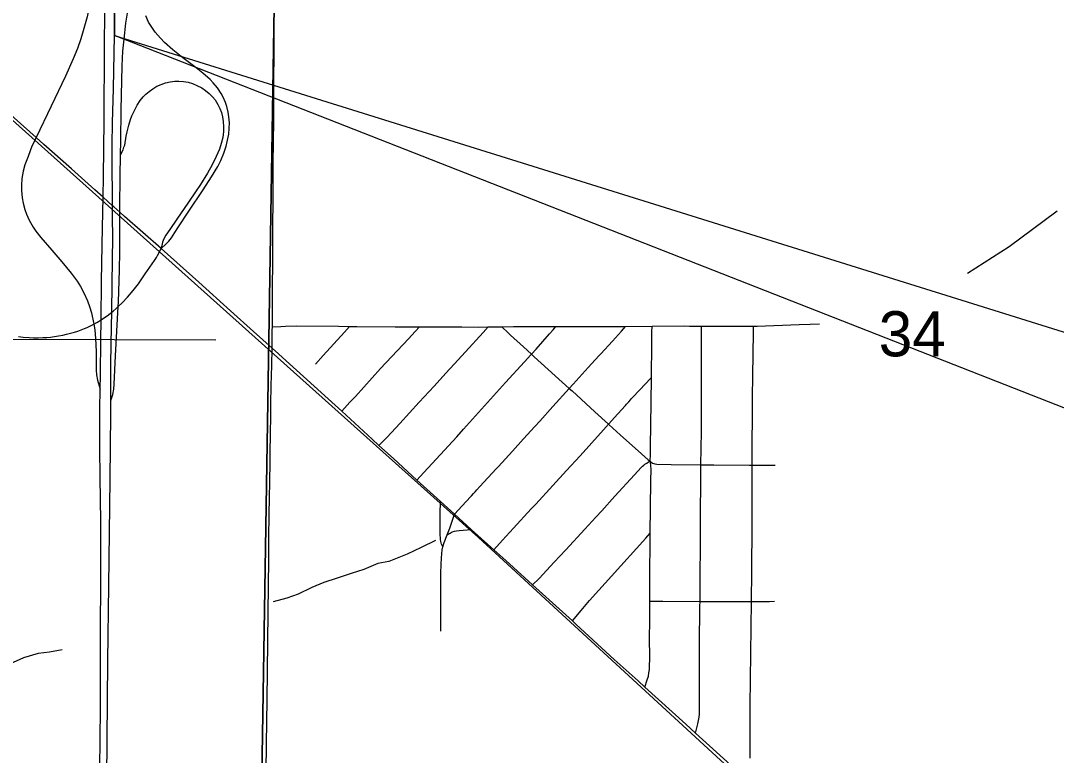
# Model space of a CAD drawing. Extents: x 0 to 40.2, y 0 to 22.
# Drawn here: x 5.526 to 6.486, y 16.354 to 17.035 of the extents above; entities that cross this region are included whole.
import ezdxf

# ---------------------------------------------------------------- set-up
doc = ezdxf.new("R2010")
doc.units = 0
for name, color, linetype in [('GM_X_Adjacent_County_Text', 7, 'Continuous'), ('GM_X_City_Street', 7, 'Continuous'), ('GM_X_Corporation', 7, 'Continuous'), ('GM_X_Major_Lake', 7, 'Continuous'), ('GM_X_Major_River', 7, 'Continuous'), ('GM_X_Major_River_Text', 7, 'Continuous'), ('GM_X_Minor_Lake', 7, 'Continuous'), ('GM_X_Rail_Line', 7, 'Continuous'), ('GM_X_Section', 7, 'Continuous'), ('GM_X_Unincorporated', 7, 'Continuous'), ('GM_X_Unincorporated_Location', 7, 'Continuous')]:
    doc.layers.add(name, color=color, linetype=linetype)

msp = doc.modelspace()

# ---------------------------------------------------------------- linework, layer by layer
at = {"layer": 'GM_X_Adjacent_County_Text'}
msp.add_lwpolyline([(5.61966, 17.93133), (5.62028, 17.89), (5.61863, 17.84377), (5.6183, 17.73735), (5.61781, 17.66349), (5.6165, 17.55078), (5.61518, 17.46691), (5.61644, 17.41988), (5.61626, 17.34851), (5.61494, 17.26994), (5.6143, 17.22476), (5.61361, 17.15512), (5.61332, 17.10722), (5.61328, 17.06369), (5.61294, 17.02079)], dxfattribs=at)
at = {"layer": 'GM_X_Corporation'}
for points in [[(4.77298, 17.26753), (5.76443, 17.25959), (5.74842, 16.25686), (4.77053, 16.2552)], [(5.76443, 17.25959), (6.76502, 17.25647), (6.76113, 16.25286), (5.74842, 16.25686)]]:
    msp.add_lwpolyline(points, close=True, dxfattribs=at)
at = {"layer": 'GM_X_Major_Lake'}
msp.add_line((5.65614, 16.82334), (5.62241, 16.85317), dxfattribs=at)
for points in [[(5.62241, 16.85317), (5.61791, 16.85715), (5.61248, 16.86195), (5.61128, 16.86303), (5.60244, 16.87093), (5.59485, 16.87772), (5.57314, 16.89725), (5.54749, 16.91986), (5.54029, 16.92629), (5.5053, 16.9575), (5.48725, 16.97355), (5.48411, 16.97635)], [(5.76512, 16.72562), (5.75908, 16.73104), (5.74185, 16.7465), (5.72053, 16.76558), (5.69106, 16.79227), (5.65614, 16.82334)], [(6.19712, 16.33296), (6.15175, 16.37401), (6.14259, 16.38229), (6.10475, 16.41674), (6.09846, 16.42246), (6.07632, 16.4425), (6.04104, 16.47484), (6.03748, 16.47807), (6.00059, 16.51153), (5.97564, 16.53414), (5.96454, 16.54407), (5.95293, 16.55446), (5.9438, 16.56279), (5.92823, 16.57701), (5.91528, 16.58882), (5.90883, 16.5947), (5.8934, 16.60874), (5.87159, 16.62859), (5.85809, 16.64083), (5.85177, 16.64657), (5.82371, 16.67254), (5.81755, 16.67823), (5.7689, 16.72223), (5.76512, 16.72562)]]:
    msp.add_lwpolyline(points, dxfattribs=at)
at = {"layer": 'GM_X_Major_River'}
msp.add_lwpolyline([(4.97994, 17.42091), (5.30245, 17.13578), (5.95038, 16.5554), (6.62714, 15.93274), (7.15702, 15.44764), (7.76806, 14.87866), (8.24495, 14.44186), (8.61841, 14.1)], dxfattribs=at)
at = {"layer": 'GM_X_Major_River_Text'}
for points in [[(5.59425, 17.08686), (5.59359, 17.07831), (5.59277, 17.06876), (5.58989, 17.04899), (5.58755, 17.03803), (5.58473, 17.02719), (5.58181, 17.01766), (5.57867, 17.00886), (5.5747, 16.99906), (5.56755, 16.98321), (5.55432, 16.95516), (5.54029, 16.92629)], [(5.60955, 16.68258), (5.61139, 16.68816), (5.6124, 16.69303), (5.61281, 16.69758), (5.61404, 16.72374), (5.61644, 16.76951), (5.61668, 16.774), (5.61772, 16.80318), (5.61801, 16.82058), (5.61791, 16.85715), (5.6179, 16.8622), (5.61829, 16.89016), (5.61868, 16.91027), (5.61892, 16.92308), (5.61924, 16.95167), (5.62023, 16.99266), (5.62086, 17.00632), (5.62186, 17.01745), (5.62364, 17.03226), (5.6256, 17.04516)], [(5.65614, 16.82334), (5.66067, 16.82747), (5.66327, 16.83008), (5.6658, 16.83318), (5.66885, 16.83824), (5.67177, 16.84265), (5.68208, 16.85804), (5.69536, 16.87759), (5.70306, 16.88966), (5.70867, 16.89937), (5.71148, 16.90491), (5.71444, 16.91176), (5.71657, 16.91827), (5.71793, 16.9237), (5.71888, 16.9292), (5.71943, 16.9348), (5.71951, 16.93977), (5.71915, 16.94536), (5.7185, 16.94966), (5.7172, 16.9551), (5.716, 16.95863), (5.7138, 16.96377), (5.71201, 16.96702), (5.70862, 16.97225), (5.70462, 16.97696), (5.70161, 16.98014), (5.69505, 16.98588), (5.68868, 16.99084), (5.67624, 17.00023), (5.66699, 17.00762), (5.65953, 17.01423), (5.65559, 17.0182), (5.65072, 17.02383), (5.64687, 17.02951), (5.64468, 17.03325), (5.64201, 17.03888)], [(5.61868, 16.91027), (5.62097, 16.91478), (5.62179, 16.91726), (5.62249, 16.91925), (5.62397, 16.92734), (5.62486, 16.93159), (5.62629, 16.93757), (5.62789, 16.94286), (5.6292, 16.94634), (5.6315, 16.95142), (5.63419, 16.95633), (5.63693, 16.96047), (5.63965, 16.96386), (5.64222, 16.96655), (5.64502, 16.969), (5.64857, 16.97151), (5.65233, 16.97369), (5.65628, 16.9755), (5.66039, 16.97692), (5.66462, 16.97791), (5.66893, 16.97845), (5.67265, 16.97855), (5.67698, 16.97824), (5.68126, 16.97745), (5.68542, 16.9762), (5.68945, 16.97456), (5.69384, 16.97223), (5.69746, 16.96982), (5.70084, 16.96708), (5.70391, 16.964), (5.70627, 16.96112), (5.70895, 16.95694), (5.7108, 16.95302), (5.71208, 16.94952), (5.71315, 16.9453), (5.71389, 16.94102), (5.71422, 16.93607), (5.71412, 16.93172), (5.71337, 16.92619), (5.71199, 16.92078), (5.71023, 16.91549), (5.7074, 16.90859), (5.70361, 16.90076), (5.69936, 16.89317), (5.69263, 16.88274), (5.68814, 16.87603), (5.68148, 16.86621)], [(5.54029, 16.92629), (5.53624, 16.91722), (5.53471, 16.91378), (5.53286, 16.90851), (5.53, 16.90095), (5.52829, 16.89498), (5.52718, 16.88824), (5.52686, 16.88204), (5.52693, 16.87707), (5.52759, 16.87026), (5.52846, 16.86536), (5.53003, 16.85936), (5.53148, 16.85526), (5.53398, 16.84958), (5.53767, 16.84311), (5.54013, 16.83955), (5.54469, 16.83364), (5.55493, 16.82194), (5.56428, 16.81112), (5.57287, 16.80048), (5.57838, 16.79296), (5.58138, 16.78824), (5.58475, 16.78231), (5.58809, 16.77496), (5.58999, 16.7697), (5.59178, 16.76376), (5.59392, 16.75322), (5.5947, 16.74789), (5.59544, 16.73984), (5.59594, 16.72803), (5.59614, 16.71064), (5.59647, 16.70621), (5.59741, 16.70119), (5.59978, 16.6931)], [(5.68148, 16.86621), (5.67094, 16.85066), (5.66419, 16.84099), (5.66067, 16.83585), (5.65879, 16.83246), (5.65757, 16.82921), (5.65614, 16.82334)]]:
    msp.add_lwpolyline(points, dxfattribs=at)
at = {"layer": 'GM_X_Minor_Lake'}
for points in [[(6.48699, 16.85795), (6.4422, 16.82491), (6.4036, 16.80011)], [(5.70689, 16.73852), (5.42354, 16.7393), (5.21054, 16.73932), (5.0119, 16.73836), (4.85265, 16.73941), (4.69415, 16.74083), (4.52087, 16.74021)], [(5.9105, 16.55274), (5.89716, 16.54613), (5.88419, 16.53989), (5.86744, 16.53333), (5.8572, 16.53122), (5.84425, 16.52574), (5.83246, 16.52213), (5.81953, 16.51779), (5.80698, 16.51382), (5.79593, 16.50906), (5.78335, 16.50282), (5.7727, 16.4992), (5.76016, 16.49598)], [(5.56462, 16.45134), (5.55286, 16.44925), (5.54224, 16.44791), (5.52856, 16.44395), (5.51561, 16.43809)]]:
    msp.add_lwpolyline(points, dxfattribs=at)
at = {"layer": 'GM_X_Rail_Line'}
for points in [[(5.75934, 16.75072), (5.75944, 16.77023), (5.7596, 16.79367), (5.75972, 16.80391), (5.75979, 16.82236), (5.75984, 16.8373), (5.76005, 16.87462), (5.7601, 16.90201), (5.76062, 16.94181), (5.76079, 16.98164), (5.76099, 17.00153), (5.761, 17.0426), (5.76146, 17.07495), (5.7616, 17.09983), (5.76172, 17.1328), (5.76197, 17.1838), (5.76192, 17.20433), (5.76214, 17.22983), (5.76207, 17.23479), (5.76181, 17.25242)], [(5.52393, 16.74171), (5.52852, 16.74125), (5.53378, 16.74084), (5.53807, 16.74064), (5.54241, 16.74062), (5.54662, 16.74072), (5.55042, 16.74098), (5.55379, 16.74126), (5.55746, 16.74172), (5.56127, 16.74233), (5.56505, 16.74309), (5.56845, 16.74386), (5.57225, 16.7448), (5.57592, 16.74584), (5.57913, 16.74684), (5.58218, 16.74798), (5.5851, 16.74911), (5.58775, 16.75027), (5.59072, 16.75162), (5.59392, 16.75322), (5.59671, 16.75478), (5.60063, 16.75724), (5.60297, 16.75871), (5.60615, 16.76097), (5.60904, 16.76311), (5.61042, 16.76426), (5.61179, 16.7654), (5.61463, 16.76781), (5.61644, 16.76951), (5.62004, 16.77287), (5.62517, 16.77821), (5.63035, 16.78433), (5.63521, 16.79073), (5.64155, 16.79992), (5.65011, 16.81221), (5.65202, 16.81506), (5.65302, 16.81697), (5.65614, 16.82334)], [(5.75908, 16.73104), (5.75932, 16.74724), (5.75934, 16.75072)], [(5.7529, 16.25157), (5.75304, 16.27475), (5.75318, 16.3133), (5.75388, 16.36427), (5.7544, 16.40467), (5.7556, 16.48609), (5.75598, 16.53519), (5.75602, 16.55508), (5.75613, 16.55881), (5.75644, 16.5731), (5.75673, 16.59611), (5.757, 16.60294), (5.75778, 16.65575), (5.7578, 16.66398), (5.75788, 16.67277), (5.75804, 16.67916), (5.75828, 16.69631), (5.75885, 16.71489), (5.75908, 16.73104)]]:
    msp.add_lwpolyline(points, dxfattribs=at)
at = {"layer": 'GM_X_Section'}
msp.add_lwpolyline([(9.21768, 15.89493), (9.21806, 15.60682), (5.61294, 17.02079)], close=True, dxfattribs=at)
at = {"layer": 'GM_X_Unincorporated'}
for points in [[(5.61131, 16.85172), (5.61128, 16.86303), (5.61127, 16.86533), (5.61079, 16.90637), (5.61083, 16.91944), (5.61131, 16.93998), (5.61215, 16.97168), (5.61294, 17.02079), (5.61328, 17.06369), (5.61332, 17.10722), (5.61361, 17.15512), (5.61384, 17.18061), (5.6143, 17.22476), (5.61494, 17.26994), (5.61575, 17.31183), (5.61626, 17.34851), (5.61654, 17.38768), (5.61644, 17.41988)], [(5.59954, 16.34117), (5.59999, 16.39651), (5.60004, 16.44688), (5.60036, 16.53765), (5.60022, 16.57062), (5.59969, 16.61103), (5.59944, 16.63838), (5.59948, 16.67442), (5.59978, 16.6931), (5.59999, 16.70612), (5.60049, 16.73846), (5.60063, 16.75724), (5.60093, 16.79317), (5.6018, 16.8429), (5.60244, 16.87093), (5.60288, 16.89014), (5.60356, 16.94175), (5.60389, 17.01015), (5.60477, 17.109)], [(5.60505, 16.25227), (5.60551, 16.2864), (5.60591, 16.33179), (5.60625, 16.36785), (5.6068, 16.44124), (5.60769, 16.51089), (5.60917, 16.60914), (5.60952, 16.67007), (5.60955, 16.68258), (5.60964, 16.71672), (5.61017, 16.75093), (5.61042, 16.76426), (5.61093, 16.79073), (5.61136, 16.83424), (5.61131, 16.85172)]]:
    msp.add_lwpolyline(points, dxfattribs=at)
at = {"layer": 'GM_X_Unincorporated_Location'}
for points in [[(5.75934, 16.75072), (5.76712, 16.75119), (5.77149, 16.75146), (5.78205, 16.75152), (5.82053, 16.75136), (5.83088, 16.75108), (5.83288, 16.75102), (5.83774, 16.75098), (5.87314, 16.75065), (5.89571, 16.75065), (5.91036, 16.75065), (5.93511, 16.75068), (5.95066, 16.75059), (5.95948, 16.75071), (5.9652, 16.75078), (5.97218, 16.75085), (5.98298, 16.75097), (6.02218, 16.75095), (6.08657, 16.75091), (6.11131, 16.75123), (6.14165, 16.75163), (6.14594, 16.75149), (6.15723, 16.75142), (6.18356, 16.75125), (6.20071, 16.75123), (6.20526, 16.75124), (6.20866, 16.75125), (6.24768, 16.75277), (6.25784, 16.75309), (6.26642, 16.75338)], [(5.7995, 16.71614), (5.80654, 16.72411), (5.8261, 16.74578), (5.83088, 16.75108)], [(5.8934, 16.60874), (5.89969, 16.61559), (5.93028, 16.64887), (5.93649, 16.65581), (5.94774, 16.66817), (5.97546, 16.69924), (5.99314, 16.71835), (5.99888, 16.72472), (5.99955, 16.72543), (6.00395, 16.7301), (6.01638, 16.74414), (6.01967, 16.74799), (6.02218, 16.75095)], [(6.10475, 16.41674), (6.10688, 16.42357), (6.10788, 16.4268), (6.10842, 16.4299), (6.10884, 16.43298), (6.10906, 16.43509), (6.10914, 16.44452), (6.10906, 16.46224), (6.10918, 16.47808), (6.10926, 16.48915), (6.10934, 16.49643), (6.1094, 16.50127), (6.10931, 16.52416), (6.10949, 16.54903), (6.10959, 16.55938), (6.11009, 16.60733), (6.11036, 16.61951), (6.11027, 16.6212), (6.1101, 16.62264), (6.1095, 16.62608), (6.10954, 16.62785), (6.10977, 16.63084), (6.10996, 16.63395), (6.11001, 16.63955), (6.11062, 16.68069), (6.11082, 16.70393), (6.1111, 16.73526), (6.11124, 16.7458), (6.11131, 16.75123)], [(6.15175, 16.37401), (6.15382, 16.38285), (6.15452, 16.38587), (6.15508, 16.38889), (6.15528, 16.39156), (6.15533, 16.39421), (6.15536, 16.45553), (6.15575, 16.49173), (6.15579, 16.49615), (6.15587, 16.50573), (6.15633, 16.56197), (6.15659, 16.62288), (6.15724, 16.65369), (6.15715, 16.74085), (6.1572, 16.74776), (6.15723, 16.75142)], [(6.2022, 16.35106), (6.20241, 16.35395), (6.20239, 16.36113), (6.20232, 16.37932), (6.20238, 16.38798), (6.20234, 16.39982), (6.20358, 16.49616), (6.20362, 16.49902), (6.20375, 16.52118), (6.20402, 16.56965), (6.20402, 16.61708), (6.20402, 16.62248), (6.204, 16.6321), (6.20413, 16.64402), (6.20431, 16.66611), (6.20451, 16.68646), (6.20453, 16.69017), (6.20467, 16.70073), (6.20478, 16.70697), (6.2051, 16.7239), (6.20524, 16.74693), (6.20526, 16.75124)], [(5.82371, 16.67254), (5.83132, 16.6808), (5.83636, 16.68627), (5.85973, 16.71201), (5.88545, 16.73964), (5.89186, 16.74652), (5.89571, 16.75065)], [(5.85809, 16.64083), (5.86476, 16.64756), (5.86564, 16.64845), (5.8776, 16.66112), (5.89535, 16.68087), (5.90931, 16.69588), (5.92015, 16.7079), (5.92781, 16.71607), (5.93831, 16.72755), (5.95462, 16.7454), (5.95948, 16.75071)], [(5.92823, 16.57701), (5.93544, 16.58488), (5.94298, 16.59311), (5.94381, 16.59407), (5.94571, 16.59617), (5.94723, 16.59791), (5.94877, 16.59952), (5.95163, 16.60266), (5.96694, 16.6191), (5.96783, 16.62005), (5.96908, 16.62137), (5.9821, 16.63534), (5.9923, 16.64693), (6.00278, 16.65836), (6.00745, 16.66332), (6.01936, 16.67687), (6.03459, 16.69362), (6.03806, 16.69745), (6.05221, 16.71305), (6.06209, 16.72382), (6.06377, 16.72564), (6.0746, 16.73743), (6.08286, 16.74673), (6.08657, 16.75091)], [(5.97218, 16.75085), (5.97782, 16.74527), (5.98003, 16.74309), (5.99203, 16.73225), (5.99955, 16.72543), (6.00217, 16.72305), (6.03459, 16.69362), (6.03712, 16.69133), (6.05825, 16.67209), (6.07095, 16.66037), (6.0715, 16.65986), (6.08166, 16.65069), (6.10168, 16.63298), (6.10765, 16.62754), (6.1095, 16.62608), (6.1106, 16.62524), (6.11189, 16.62445), (6.11286, 16.62408), (6.11384, 16.6238), (6.11579, 16.62353), (6.12892, 16.62312), (6.15659, 16.62288), (6.16873, 16.62278), (6.20166, 16.62248), (6.20402, 16.62248), (6.21463, 16.62247), (6.22544, 16.62241)], [(5.96454, 16.54407), (5.97277, 16.55311), (5.98274, 16.56406), (5.99932, 16.58211), (6.001, 16.58383), (6.00351, 16.58649), (6.01923, 16.60358), (6.03197, 16.61754), (6.04455, 16.6312), (6.0663, 16.65527), (6.07095, 16.66037), (6.07971, 16.66997), (6.08676, 16.6779), (6.08777, 16.67912), (6.0898, 16.68128), (6.09142, 16.6831), (6.09241, 16.68425), (6.10088, 16.69342), (6.10394, 16.69666), (6.11082, 16.70393)], [(6.00059, 16.51153), (6.00669, 16.51758), (6.02062, 16.53259), (6.02581, 16.53808), (6.03142, 16.5441), (6.04916, 16.56332), (6.05932, 16.57436), (6.06469, 16.58024), (6.07672, 16.59365), (6.09503, 16.61369), (6.10129, 16.6204), (6.10261, 16.62164), (6.10358, 16.62249), (6.10471, 16.62333), (6.10635, 16.62437), (6.10816, 16.62548), (6.1095, 16.62608)], [(5.91741, 16.54687), (5.91615, 16.54942), (5.91552, 16.55175), (5.91523, 16.55348), (5.91512, 16.55506), (5.91495, 16.55754), (5.91495, 16.56014), (5.91502, 16.57041), (5.91482, 16.57406), (5.91492, 16.57737), (5.91528, 16.58882)], [(5.9155, 16.46853), (5.91559, 16.47474), (5.91568, 16.50993), (5.91561, 16.51752), (5.91559, 16.52251), (5.91569, 16.53055), (5.91612, 16.5367), (5.91689, 16.54404), (5.91741, 16.54687), (5.91874, 16.55094), (5.92134, 16.55785), (5.92375, 16.56421), (5.92603, 16.57073), (5.92823, 16.57701)], [(5.92134, 16.55785), (5.92408, 16.55961), (5.92605, 16.5606), (5.92813, 16.56126), (5.92999, 16.56159), (5.93251, 16.56181), (5.9438, 16.56279)], [(6.03748, 16.47807), (6.04558, 16.4877), (6.05343, 16.49703), (6.06207, 16.50675), (6.07368, 16.51972), (6.10552, 16.55488), (6.10959, 16.55938)], [(6.10934, 16.49643), (6.11385, 16.49648), (6.12123, 16.49654), (6.15579, 16.49615), (6.15857, 16.49612), (6.17845, 16.49607), (6.19909, 16.49615), (6.20358, 16.49616), (6.22008, 16.49621), (6.22492, 16.49631)]]:
    msp.add_lwpolyline(points, dxfattribs=at)

# ---------------------------------------------------------------- texts
at = {"layer": 'GM_X_City_Street'}
msp.add_text('34', height=0.041856, rotation=0.00001, dxfattribs=at).set_placement((6.32143, 16.72337))

doc.saveas('drawing.dxf')
